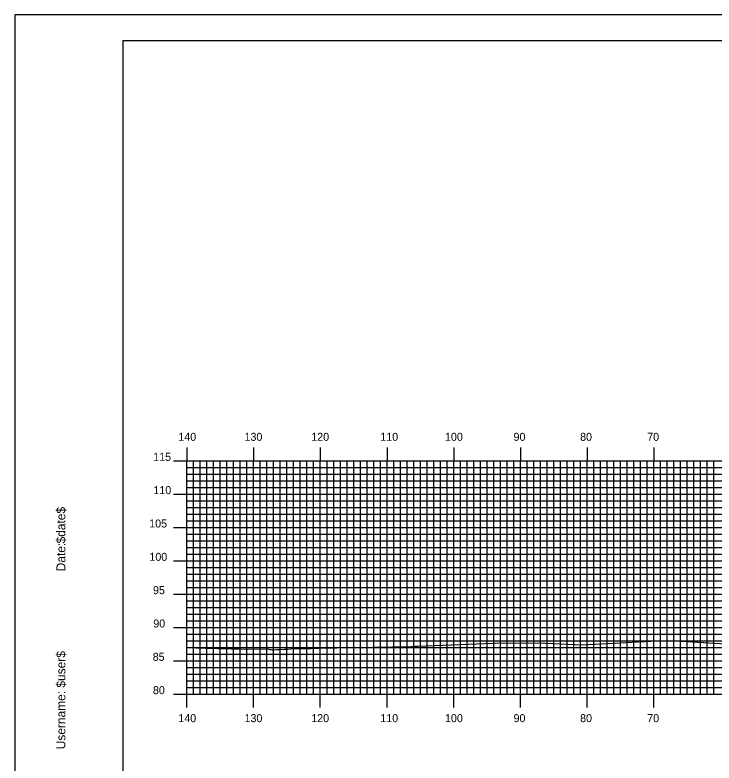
# Model space of a CAD drawing. Extents: x 1762972 to 1763315, y 442591 to 442811.
# Drawn here: x 1762971.5 to 1763076.3, y 442698.3 to 442810.5 of the extents above; entities that cross this region are included whole.
import ezdxf

# ---------------------------------------------------------------- set-up
doc = ezdxf.new("R2010")
doc.units = 0
for name, color, linetype in [('BORDER', 7, 'Continuous'), ('H_V ANNOTATION', 7, 'Continuous'), ('MAJOR', 7, 'Continuous'), ('MINOR', 7, 'Continuous'), ('PLOT BOUNDARY', 7, 'Continuous'), ('S_Roadway_Centerline', 7, 'Continuous')]:
    doc.layers.add(name, color=color, linetype=linetype)

msp = doc.modelspace()

# ---------------------------------------------------------------- linework, layer by layer
at = {"layer": 'BORDER'}
msp.add_lwpolyline([(1762987.69, 442596.67), (1763307.69, 442596.67), (1763307.69, 442806.67), (1762987.69, 442806.67)], close=True, dxfattribs=at)
at = {"layer": 'MAJOR'}
for p, q in [((1762997.29, 442745.67), (1762997.29, 442743.67)), ((1763007.29, 442745.67), (1763007.29, 442743.67)), ((1763017.29, 442745.67), (1763017.29, 442743.67)), ((1763027.29, 442745.67), (1763027.29, 442743.67)), ((1763037.29, 442745.67), (1763037.29, 442743.67)), ((1763047.29, 442745.67), (1763047.29, 442743.67)), ((1763057.29, 442745.67), (1763057.29, 442743.67)), ((1763067.29, 442745.67), (1763067.29, 442743.67)), ((1762995.29, 442743.67), (1762997.29, 442743.67)), ((1762997.29, 442743.67), (1763277.29, 442743.67)), ((1762997.29, 442708.67), (1762997.29, 442743.67)), ((1762997.29, 442708.67), (1762997.29, 442743.67)), ((1762997.29, 442743.67), (1763277.29, 442743.67)), ((1763007.29, 442708.67), (1763007.29, 442743.67)), ((1763017.29, 442708.67), (1763017.29, 442743.67)), ((1763027.29, 442708.67), (1763027.29, 442743.67)), ((1763037.29, 442708.67), (1763037.29, 442743.67)), ((1763047.29, 442708.67), (1763047.29, 442743.67)), ((1763057.29, 442708.67), (1763057.29, 442743.67)), ((1763067.29, 442708.67), (1763067.29, 442743.67)), ((1762995.29, 442738.67), (1762997.29, 442738.67)), ((1762997.29, 442738.67), (1763277.29, 442738.67)), ((1762995.29, 442733.67), (1762997.29, 442733.67)), ((1762997.29, 442733.67), (1763277.29, 442733.67)), ((1762995.29, 442728.67), (1762997.29, 442728.67)), ((1762997.29, 442728.67), (1763277.29, 442728.67)), ((1762995.29, 442723.67), (1762997.29, 442723.67)), ((1762997.29, 442723.67), (1763277.29, 442723.67)), ((1762995.29, 442718.67), (1762997.29, 442718.67)), ((1762997.29, 442718.67), (1763277.29, 442718.67)), ((1762995.29, 442713.67), (1762997.29, 442713.67)), ((1762997.29, 442713.67), (1763277.29, 442713.67)), ((1762995.29, 442708.67), (1762997.29, 442708.67)), ((1762997.29, 442708.67), (1763277.29, 442708.67)), ((1762997.29, 442708.67), (1763277.29, 442708.67)), ((1762997.29, 442706.66), (1762997.29, 442708.67)), ((1763007.29, 442706.66), (1763007.29, 442708.67)), ((1763017.29, 442706.66), (1763017.29, 442708.67)), ((1763027.29, 442706.66), (1763027.29, 442708.67)), ((1763037.29, 442706.66), (1763037.29, 442708.67)), ((1763047.29, 442706.66), (1763047.29, 442708.67)), ((1763057.29, 442706.66), (1763057.29, 442708.67)), ((1763067.29, 442706.66), (1763067.29, 442708.67))]:
    msp.add_line(p, q, dxfattribs=at)
at = {"layer": 'MINOR'}
for p, q in [((1762998.29, 442708.67), (1762998.29, 442743.67)), ((1762999.29, 442708.67), (1762999.29, 442743.67)), ((1763000.29, 442708.67), (1763000.29, 442743.67)), ((1763001.29, 442708.67), (1763001.29, 442743.67)), ((1763002.29, 442708.67), (1763002.29, 442743.67)), ((1763003.29, 442708.67), (1763003.29, 442743.67)), ((1763004.29, 442708.67), (1763004.29, 442743.67)), ((1763005.29, 442708.67), (1763005.29, 442743.67)), ((1763006.29, 442708.67), (1763006.29, 442743.67)), ((1763008.29, 442708.67), (1763008.29, 442743.67)), ((1763009.29, 442708.67), (1763009.29, 442743.67)), ((1763010.29, 442708.67), (1763010.29, 442743.67)), ((1763011.29, 442708.67), (1763011.29, 442743.67)), ((1763012.29, 442708.67), (1763012.29, 442743.67)), ((1763013.29, 442708.67), (1763013.29, 442743.67)), ((1763014.29, 442708.67), (1763014.29, 442743.67)), ((1763015.29, 442708.67), (1763015.29, 442743.67)), ((1763016.29, 442708.67), (1763016.29, 442743.67)), ((1763018.29, 442708.67), (1763018.29, 442743.67)), ((1763019.29, 442708.67), (1763019.29, 442743.67)), ((1763020.29, 442708.67), (1763020.29, 442743.67)), ((1763021.29, 442708.67), (1763021.29, 442743.67)), ((1763022.29, 442708.67), (1763022.29, 442743.67)), ((1763023.29, 442708.67), (1763023.29, 442743.67)), ((1763024.29, 442708.67), (1763024.29, 442743.67)), ((1763025.29, 442708.67), (1763025.29, 442743.67)), ((1763026.29, 442708.67), (1763026.29, 442743.67)), ((1763028.29, 442708.67), (1763028.29, 442743.67)), ((1763029.29, 442708.67), (1763029.29, 442743.67)), ((1763030.29, 442708.67), (1763030.29, 442743.67)), ((1763031.29, 442708.67), (1763031.29, 442743.67)), ((1763032.29, 442708.67), (1763032.29, 442743.67)), ((1763033.29, 442708.67), (1763033.29, 442743.67)), ((1763034.29, 442708.67), (1763034.29, 442743.67)), ((1763035.29, 442708.67), (1763035.29, 442743.67)), ((1763036.29, 442708.67), (1763036.29, 442743.67)), ((1763038.29, 442708.67), (1763038.29, 442743.67)), ((1763039.29, 442708.67), (1763039.29, 442743.67)), ((1763040.29, 442708.67), (1763040.29, 442743.67)), ((1763041.29, 442708.67), (1763041.29, 442743.67)), ((1763042.29, 442708.67), (1763042.29, 442743.67)), ((1763043.29, 442708.67), (1763043.29, 442743.67)), ((1763044.29, 442708.67), (1763044.29, 442743.67)), ((1763045.29, 442708.67), (1763045.29, 442743.67)), ((1763046.29, 442708.67), (1763046.29, 442743.67)), ((1763048.29, 442708.67), (1763048.29, 442743.67)), ((1763049.29, 442708.67), (1763049.29, 442743.67)), ((1763050.29, 442708.67), (1763050.29, 442743.67)), ((1763051.29, 442708.67), (1763051.29, 442743.67)), ((1763052.29, 442708.67), (1763052.29, 442743.67)), ((1763053.29, 442708.67), (1763053.29, 442743.67)), ((1763054.29, 442708.67), (1763054.29, 442743.67)), ((1763055.29, 442708.67), (1763055.29, 442743.67)), ((1763056.29, 442708.67), (1763056.29, 442743.67)), ((1763058.29, 442708.67), (1763058.29, 442743.67)), ((1763059.29, 442708.67), (1763059.29, 442743.67)), ((1763060.29, 442708.67), (1763060.29, 442743.67)), ((1763061.29, 442708.67), (1763061.29, 442743.67)), ((1763062.29, 442708.67), (1763062.29, 442743.67)), ((1763063.29, 442708.67), (1763063.29, 442743.67)), ((1763064.29, 442708.67), (1763064.29, 442743.67)), ((1763065.29, 442708.67), (1763065.29, 442743.67)), ((1763066.29, 442708.67), (1763066.29, 442743.67)), ((1763068.29, 442708.67), (1763068.29, 442743.67)), ((1763069.29, 442708.67), (1763069.29, 442743.67)), ((1763070.29, 442708.67), (1763070.29, 442743.67)), ((1763071.29, 442708.67), (1763071.29, 442743.67)), ((1763072.29, 442708.67), (1763072.29, 442743.67)), ((1763073.29, 442708.67), (1763073.29, 442743.67)), ((1763074.29, 442708.67), (1763074.29, 442743.67)), ((1763075.29, 442708.67), (1763075.29, 442743.67)), ((1763076.29, 442708.67), (1763076.29, 442743.67)), ((1762997.29, 442742.67), (1763277.29, 442742.67)), ((1762997.29, 442742.67), (1762999.3, 442742.67)), ((1762997.29, 442741.67), (1763277.29, 442741.67)), ((1762997.29, 442741.67), (1762999.3, 442741.67)), ((1762997.29, 442740.67), (1763277.29, 442740.67)), ((1762997.29, 442740.67), (1762999.3, 442740.67)), ((1762997.29, 442739.67), (1763277.29, 442739.67)), ((1762997.29, 442739.67), (1762999.3, 442739.67)), ((1762997.29, 442737.67), (1763277.29, 442737.67)), ((1762997.29, 442737.67), (1762999.3, 442737.67)), ((1762997.29, 442736.67), (1763277.29, 442736.67)), ((1762997.29, 442736.67), (1762999.3, 442736.67)), ((1762997.29, 442735.67), (1763277.29, 442735.67)), ((1762997.29, 442735.67), (1762999.3, 442735.67)), ((1762997.29, 442734.67), (1763277.29, 442734.67)), ((1762997.29, 442734.67), (1762999.3, 442734.67)), ((1762997.29, 442732.67), (1763277.29, 442732.67)), ((1762997.29, 442732.67), (1762999.3, 442732.67)), ((1762997.29, 442731.67), (1763277.29, 442731.67)), ((1762997.29, 442731.67), (1762999.3, 442731.67)), ((1762997.29, 442730.67), (1763277.29, 442730.67)), ((1762997.29, 442730.67), (1762999.3, 442730.67)), ((1762997.29, 442729.67), (1763277.29, 442729.67)), ((1762997.29, 442729.67), (1762999.3, 442729.67)), ((1762997.29, 442727.67), (1763277.29, 442727.67)), ((1762997.29, 442727.67), (1762999.3, 442727.67)), ((1762997.29, 442726.67), (1763277.29, 442726.67)), ((1762997.29, 442726.67), (1762999.3, 442726.67)), ((1762997.29, 442725.67), (1763277.29, 442725.67)), ((1762997.29, 442725.67), (1762999.3, 442725.67)), ((1762997.29, 442724.67), (1763277.29, 442724.67)), ((1762997.29, 442724.67), (1762999.3, 442724.67)), ((1762997.29, 442722.67), (1763277.29, 442722.67)), ((1762997.29, 442722.67), (1762999.3, 442722.67)), ((1762997.29, 442721.67), (1763277.29, 442721.67)), ((1762997.29, 442721.67), (1762999.3, 442721.67)), ((1762997.29, 442720.67), (1763277.29, 442720.67)), ((1762997.29, 442720.67), (1762999.3, 442720.67)), ((1762997.29, 442719.67), (1763277.29, 442719.67)), ((1762997.29, 442719.67), (1762999.3, 442719.67)), ((1762997.29, 442717.67), (1763277.29, 442717.67)), ((1762997.29, 442717.67), (1762999.3, 442717.67)), ((1762997.29, 442716.67), (1763277.29, 442716.67)), ((1762997.29, 442716.67), (1762999.3, 442716.67)), ((1762997.29, 442715.67), (1763277.29, 442715.67)), ((1762997.29, 442715.67), (1762999.3, 442715.67)), ((1762997.29, 442714.67), (1763277.29, 442714.67)), ((1762997.29, 442714.67), (1762999.3, 442714.67)), ((1762997.29, 442712.67), (1763277.29, 442712.67)), ((1762997.29, 442712.67), (1762999.3, 442712.67)), ((1762997.29, 442711.67), (1763277.29, 442711.67)), ((1762997.29, 442711.67), (1762999.3, 442711.67)), ((1762997.29, 442710.67), (1763277.29, 442710.67)), ((1762997.29, 442710.67), (1762999.3, 442710.67)), ((1762997.29, 442709.67), (1763277.29, 442709.67)), ((1762997.29, 442709.67), (1762999.3, 442709.67))]:
    msp.add_line(p, q, dxfattribs=at)
at = {"layer": 'PLOT BOUNDARY'}
msp.add_lwpolyline([(1762971.51, 442590.55), (1763311.51, 442590.55), (1763311.51, 442810.55), (1762971.51, 442810.55)], close=True, dxfattribs=at)
at = {"layer": 'S_Roadway_Centerline'}
msp.add_lwpolyline([(1762997.29, 442715.67), (1763000.07, 442715.57), (1763000.92, 442715.55), (1763001.86, 442715.53), (1763002.89, 442715.51), (1763003.99, 442715.48), (1763005.15, 442715.45), (1763006.36, 442715.42), (1763009.36, 442715.46), (1763009.57, 442715.42), (1763009.71, 442715.39), (1763009.88, 442715.37), (1763010.09, 442715.33), (1763010.11, 442715.33), (1763010.73, 442715.36), (1763011.34, 442715.38), (1763011.9, 442715.41), (1763012.4, 442715.43), (1763012.85, 442715.45), (1763015.27, 442715.52), (1763015.46, 442715.52), (1763015.63, 442715.52), (1763015.79, 442715.53), (1763015.92, 442715.53), (1763016.3, 442715.55), (1763016.67, 442715.56), (1763017.04, 442715.58), (1763030.84, 442715.82), (1763030.91, 442715.82), (1763030.97, 442715.82), (1763031.03, 442715.82), (1763031.07, 442715.83), (1763031.11, 442715.83), (1763031.14, 442715.83), (1763031.17, 442715.83), (1763031.19, 442715.83), (1763031.21, 442715.83), (1763031.22, 442715.83), (1763031.23, 442715.83), (1763031.24, 442715.83), (1763031.26, 442715.83), (1763031.27, 442715.83), (1763031.28, 442715.83), (1763031.48, 442715.85), (1763031.87, 442715.87), (1763044.51, 442716.39), (1763051.02, 442716.3), (1763056.66, 442716.08), (1763067.74, 442716.65), (1763069.72, 442716.7), (1763080.53, 442716.05)], dxfattribs=at)

# ---------------------------------------------------------------- texts
at = {"layer": 'BORDER'}
for s, p in [('$date$', (1762979.06, 442731.28)), ('Date:', (1762979.06, 442727.1)), ('$user$', (1762979.06, 442709.65)), ('Username:', (1762979.06, 442700.4))]:
    msp.add_text(s, height=1.339, rotation=90, dxfattribs=at).set_placement(p)
at = {"layer": 'H_V ANNOTATION'}
for s, p in [('140', (1762996, 442746.67)), ('130', (1763005.92, 442746.67)), ('120', (1763015.93, 442746.67)), ('110', (1763026.28, 442746.67)), ('100', (1763035.98, 442746.67)), ('90', (1763046.26, 442746.67)), ('80', (1763056.24, 442746.67)), ('70', (1763066.3, 442746.67)), ('115', (1762992.23, 442743.67)), ('110', (1762992.26, 442738.67)), ('105', (1762991.63, 442733.67)), ('100', (1762991.66, 442728.67)), ('95', (1762992.2, 442723.67)), ('90', (1762992.24, 442718.67)), ('85', (1762992.16, 442713.67)), ('80', (1762992.19, 442708.67)), ('140', (1762996, 442704.47)), ('130', (1763005.92, 442704.47)), ('120', (1763015.93, 442704.47)), ('110', (1763026.28, 442704.47)), ('100', (1763035.98, 442704.47)), ('90', (1763046.26, 442704.47)), ('80', (1763056.24, 442704.47)), ('70', (1763066.3, 442704.47))]:
    msp.add_text(s, height=1.2, dxfattribs=at).set_placement(p)
at = {"layer": 'MAJOR'}
msp.add_text('-', height=0.012, dxfattribs=at).set_placement((1762997.28, 442708.67))

doc.saveas('drawing.dxf')
